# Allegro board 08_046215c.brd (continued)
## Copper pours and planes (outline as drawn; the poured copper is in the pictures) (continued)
GND on L2_GROUND: 12.9,24.98 13.49,25.16 14.2,25.16 14.2,26.76 13.46,26.76 12.98,26.93 9.96,26.93 9.12,26.81 8.38,26.38 4.83,22.82 0.51,22.82 0.51,30.06 0.63,29.93 10.41,29.93 10.41,31.58 18.8,31.58 22.48,35.27 25.27,35.27 24.77,34.76 24.77,32.73 25.65,32.73 25.78,32.85 25.78,34 26.42,34.63 26.67,34.63 27.3,34 27.3,32.73 28.32,32.73 28.32,34.63 27.18,35.77 27.05,35.77 27.05,43.65 26.67,44.03 22.1,44.03 19.43,46.7 14.99,46.7 14.99,55.33 9.78,55.33 9.78,48.73 0.51,48.73 0.51,65.49 27.43,65.49 27.56,65.62 27.56,68.29 27.69,68.41 75.95,68.41 75.95,0.47 22.86,0.47 22.86,3.14 11.94,3.14 11.94,5.29 0.51,5.29 0.51,20.84 4.93,20.84 5.52,20.95 6.05,21.25 9.65,24.85 9.78,24.95 9.93,24.98 ; 4 cut-outs
GND on L3_SIGNAL: 23.5,0.34 23.5,0.47 22.99,0.47 22.99,3.14 11.94,3.14 11.94,5.42 0.51,5.42 0.51,29.3 11.05,29.3 11.05,34.25 24,34.25 26.29,36.66 26.92,37.3 29.21,34.25 29.21,31.33 31.37,30.44 31.37,26.63 33.91,26.63 33.91,32.85 32.13,33.62 32.13,41.49 32.77,41.49 32.77,43.01 33.27,43.01 33.27,51.01 29.97,51.01 27.56,57.49 27.56,63.59 25.02,63.59 25.02,63.33 24.36,62.67 24.36,52.53 25.27,48.22 27.56,48.22 27.56,44.41 11.18,44.41 11.18,49.36 0.51,49.36 0.51,64.98 27.56,64.98 27.56,68.54 27.69,68.67 75.95,68.67 75.95,49.87 75.82,49.87 75.82,0.34 ; 6 cut-outs
GND on L4_GROUND, L7_GROUND: 27.56,68.41 75.95,68.41 75.95,0.47 22.86,0.47 22.86,3.14 11.94,3.14 11.94,5.29 0.51,5.29 0.51,65.49 27.43,65.49 27.56,65.62
GND on L6_POWER: 0.38,58.89 13.84,58.89 13.84,61.17 34.29,61.17 34.29,55.21 25.15,55.21 24.38,54.44 24.38,35.27 25.27,34.38 27.43,34.38 27.43,34.25 27.94,33.74 39.88,33.74 39.88,25.23 24.13,25.23 24.13,5.93 24,5.8 18.29,5.8 18.29,8.47 13.21,8.47 13.21,11.39 13.08,11.52 10.03,11.52 10.03,17.36 0.38,17.36
GND on L9_GROUND: 27.56,68.41 75.95,68.41 75.95,0.47 23.37,0.47 23.37,3.14 11.94,3.14 11.94,5.29 0.51,5.29 0.51,65.49 27.56,65.49
GND on L10_SIGNAL: 27.56,68.41 75.95,68.41 75.95,0.47 23.37,0.47 23.37,3.14 11.94,3.14 11.94,5.29 0.51,5.29 0.51,65.49 27.56,65.49 ; 19 cut-outs
GND on L11_GROUND: 27.56,68.41 75.95,68.41 75.95,0.47 23.37,0.47 23.37,3.14 11.94,3.14 11.94,5.29 0.51,5.29 0.51,65.49 27.56,65.49 ; 1 cut-out
SVDD12 on TOP (solid shape): 32.7,56.33 33.3,56.33 33.84,55.78 33.84,55.69 33.93,55.69 34.61,55.01 34.61,54.99 34.65,54.73 34.8,54.52 34.8,51.01 32.95,51.01 32.51,51.27 32.07,51.01 31.68,51.01 31.24,51.27 30.8,51.01 30.48,51.01 30.1,51.4 30.1,55.33 30.61,55.84 32.39,55.84 32.47,55.93 32.55,55.93 32.55,56.26 32.62,56.33
SVDD12 on L8_POWER: 29.46,55.46 31.24,57.24 37.72,57.24 39.5,55.46 39.5,35.39 29.46,35.39
VCC on L5_POWER: 0.63,50.25 0.63,65.37 25.53,65.37 25.53,62.95 19.3,62.95 19.3,50.25
VDDA12 on TOP: 20.07,53.17 20.07,55.46 20.45,55.84 22.35,55.84 22.48,55.97 22.48,56.22 22.61,56.35 23.37,56.35 23.62,56.09 23.62,54.82 23.37,54.57 23.37,53.3 23.11,53.05 20.19,53.05
VDDA12 on L8_POWER: 24.38,57.36 26.42,55.33 26.42,42.51 25.65,41.74 20.32,41.74 19.56,42.51 19.56,55.71 21.21,57.36
VDDA25 on TOP (solid shape): 22,43.39 24.06,41.92 25.1,40.97 25.1,40.97 25.16,40.9 25.23,40.85 25.24,40.84 25.4,40.7 25.58,40.52 25.59,40.51 25.65,40.4 25.75,40.34 25.76,40.34 26.08,40.02 26.09,40.01 26.15,39.9 26.25,39.84 26.26,39.84 26.42,39.68 26.42,39.02 26.42,39 26.24,38.82 26.23,38.82 26.15,38.76 26.09,38.68 26.09,38.67 25.74,38.32 25.73,38.32 25.65,38.26 25.6,38.18 25.59,38.18 25.4,37.98 25.2,37.81 25.16,37.77 25.12,37.73 24.05,36.76 21.97,35.27 20.95,35.27 20.95,37.68 23.75,37.68 25.27,38.67 25.35,38.72 25.52,38.72 25.55,38.72 25.62,38.76 25.67,38.81 25.7,38.88 25.7,38.95 25.7,39.71 25.71,39.74 25.66,39.89 25.53,39.96 25.37,39.97 25.28,40.01 24,40.85 20.95,40.85 20.95,43.39
VDDA25 on TOP: 9.4,56.73 9.65,56.73 9.65,55.08 14.35,55.08 14.35,51.27 11.05,51.27 11.05,52.92 9.02,52.92 9.02,55.21 9.4,55.59
VDDA25 on TOP: 8.64,43.39 8.64,35.27 20.95,35.27 20.95,37.81 20.19,37.81 20.19,40.85 20.95,40.85 20.95,43.39
VDDA25 on L2_GROUND: 10.03,31.96 18.67,31.96 22.48,35.77 26.54,35.77 26.54,43.52 21.46,43.52 18.67,46.32 14.48,46.32 14.48,55.08 10.16,55.08 10.16,48.35 0.51,48.35 0.51,40.35 17.14,40.35 17.53,38.7 17.14,37.04 14.61,37.04 14.61,38.31 0.51,38.31 0.51,30.31 10.03,30.31 ; 1 cut-out
VDDA25 on L3_SIGNAL: 8.64,43.39 27.05,43.39 27.05,37.81 26.92,37.81 24.38,35.27 8.64,35.27
VDDC12 on TOP: 23.88,54.57 27.69,52.41 27.69,47.71 23.88,50.13
VDDC12 on L6_POWER: 30.48,43.9 28.07,41.49 28.07,35.65 27.69,35.65 27.43,35.9 27.43,36.28 26.92,36.92 26.92,41.24 27.43,41.74 27.43,43.39 26.04,44.79 26.04,51.27 26.92,52.16 28.7,52.16 30.48,50.38
VIN_12V on BOTTOM (solid shape): 54.48,33.49 53.09,33.49 53.09,32.85 50.67,32.85 50.67,31.96 50.16,31.94 49.96,31.92 49.78,31.94 49.53,31.96 49.53,32.73 49.15,32.73 49.15,33.74 51.56,33.74 52.58,34.76 53.09,35.39 54.48,35.39
VIN_12V on BOTTOM: 51.31,19.14 51.31,14.57 54.74,14.57 54.74,19.14
VIN_12V on BOTTOM: 53.85,45.3 53.85,44.16 54.61,43.78 54.61,42 54.99,41.62 55.75,41.62 55.75,43.27 55.37,43.65 55.37,45.68 54.36,45.68 54.36,45.3
VIN_12V on BOTTOM: 40.89,36.03 42.29,34.63 43.05,34 43.05,31.2 42.67,31.2 42.16,31.71 42.16,33.62 41.15,33.62 41.15,33.87 41.02,34 38.86,34 38.86,36.03
VIN_12V on L8_POWER: 50.16,13.93 50.16,19.14 41.28,19.26 41.28,20.66 41.02,52.28 41.02,56.09 38.86,58.25 21.46,58.25 18.92,55.71 18.92,52.79 18.41,52.28 15.11,52.28 13.84,53.55 12.57,53.55 8,58.13 8,65.49 10.16,65.49 10.16,58.63 13.34,55.46 16.89,55.46 21.84,60.41 40,60.41 43.05,57.36 43.05,52.79 53.47,52.79 53.98,52.28 53.98,48.98 54.74,48.09 54.74,45.93 55.88,44.79 55.88,13.93
3P3VAUX on TOP: 72.9,56.73 73.91,56.73 74.42,56.35 74.42,55.59 73.91,55.08 72.9,55.08
3P3VAUX on L5_POWER: 68.83,66.25 68.83,21.55 68.45,21.17 68.45,19.65 68.83,19.26 75.95,19.26 75.95,66.25
AD9508_VDD on TOP: 43.81,12.91 43.81,10.5 45.59,10.5 45.59,12.91
AD9508_VDD on TOP: 49.15,13.04 51.05,13.04 51.05,11.77 50.04,11.77 50.04,10.5 48.77,10.5 48.77,12.15 48.26,12.15 48.26,13.04 48.13,13.17 48.13,16.09 50.04,16.09 50.29,15.84 50.29,14.95 49.53,14.18 49.15,14.18 49.02,14.06 49.02,13.17
AD9508_VDD on L5_POWER: 41.28,1.74 52.45,1.74 52.45,12.66 43.18,12.66 43.18,10.76 41.28,10.76
ADCLK914VCC on TOP: 11.18,20.53 12.45,20.53 12.45,19.39 13.59,19.39 13.59,19.01 11.56,19.01 11.56,20.03 11.18,20.03
ADCLK914VCC on L8_POWER: 10.29,6.82 10.29,22.44 18.03,22.44 18.03,17.74 16.26,17.74 16.26,6.82
ADF4355_VDD_3V3 on TOP: 10.79,14.06 12.83,14.06 12.83,12.53 10.79,12.53
ADF4355_VDD_3V3 on L10_SIGNAL: 32.13,6.44 33.27,7.58 33.27,13.17 38.23,13.17 38.99,12.41 45.85,12.41 46.99,13.55 46.99,18.38 46.61,18.76 31.12,18.76 28.32,15.96 24.77,15.96 24.26,16.34 24.26,18.38 24,18.63 10.67,18.63 8.89,16.85 8.89,11.64 14.1,6.44
ADF4355_VRF_3V3 on TOP: 18.92,11.39 18.92,9.49 15.75,9.49 15.75,11.39
ADF4355_VRF_3V3 on TOP: 17.14,15.45 19.69,15.45 19.69,15.71 20.57,15.71 20.57,15.45 21.59,15.45 21.59,14.06 21.34,13.8 21.34,13.42 21.46,13.3 22.23,13.3 22.23,12.91 21.08,12.91 20.83,13.17 20.83,13.8 18.54,13.8 18.54,13.42 17.14,13.42
ADF4355_VRF_3V3 on BOTTOM: 16.51,11.52 16.51,9.74 15.24,8.47 15.24,6.56 13.97,5.29 11.81,5.29 11.81,7.33 13.46,7.33 13.46,9.49 15.49,11.52
ADF4355_VRF_3V3 on L5_POWER: 20.7,15.58 21.72,14.57 21.72,5.55 18.16,5.55 18.16,8.22 12.95,8.22 12.95,15.96 15.37,18.38 20.7,18.38
ADF4355_VVCO_5V on TOP: 37.85,6.18 39.75,6.18 39.75,4.91 37.59,4.91 37.34,5.04 37.34,5.8
ADF4355_VVCO_5V on TOP: 21.59,7.83 23.5,7.83 23.75,8.09 23.75,8.85 22.48,8.85 22.23,9.1 22.23,9.36 20.95,9.36 20.83,9.23 20.83,8.09 21.59,8.09
ADF4355_VVCO_5V on L8_POWER: 19.43,3.14 39.75,3.14 39.75,7.96 23.62,7.96 23.62,24.73 18.92,24.73 18.92,7.58 19.43,7.07
ADP5054_1V2 on TOP (solid shape): 57.91,38.06 57.15,38.06 56.73,37.64 56.57,37.64 56.57,37.48 55.24,36.16 54.36,36.16 53.34,37.17 53.34,37.55 52.7,38.19 52.7,39.33 57.91,39.33
ADP5054_1V2 on BOTTOM: 55.88,38.06 55.88,35.77 53.47,35.77 53.47,38.06
ADP5054_1V2 on L5_POWER: 34.8,45.55 40.39,40.35 43.31,40.35 46.74,43.78 53.47,43.78 57.02,40.22 57.02,34.5 56.77,34.25 28.19,34.25 28.19,41.49 32.39,45.55
ADP5054_1V5 on TOP: 30.61,58.13 32.64,58.13 33.02,58.51 34.92,58.51 34.92,59.52 33.4,61.05 30.48,61.05 30.1,60.67 30.1,58.63
ADP5054_1V5 on TOP: 20.57,58.13 22.61,58.13 22.61,57.62 23.37,57.62 23.62,57.87 23.62,58.38 23.75,58.51 24.89,58.51 24.89,61.43 20.45,61.43 20.07,61.05 20.07,58.63
ADP5054_1V5 on BOTTOM: 40.39,42.51 40.39,42.89 37.72,42.89 37.72,43.39 36.83,43.39 36.83,44.16 37.85,44.16 37.85,45.3 40.89,45.3 40.89,43.78 41.15,43.78 42.04,42.89 42.04,42.51
ADP5054_1V5 on L5_POWER: 37.72,44.66 37.72,43.9 39.37,42.25 43.31,42.25 43.81,42.76 43.81,53.05 34.29,62.57 21.59,62.57 20.7,61.68 20.7,58.63 26.67,52.67 29.72,52.67
ADP5054_3V8 on TOP: 9.65,60.92 9.65,60.29 9.14,60.29 9.14,59.02 7.62,59.02 7.62,58.63 6.1,58.63 5.21,59.52 5.21,61.17 9.4,61.17
ADP5054_3V8 on TOP: 34.29,63.84 35.69,63.84 36.2,64.35 36.2,64.86 36.32,64.98 38.1,64.98 38.61,64.48 42.29,64.48 42.42,64.35 42.42,63.46 41.53,62.57 38.61,62.57 37.97,63.21 34.29,63.21
ADP5054_3V8 on TOP: 14.22,5.04 14.22,3.01 16.89,3.01 16.89,5.04
ADP5054_3V8 on BOTTOM: 54.99,20.66 57.66,20.66 57.66,21.04 59.31,21.04 59.31,18.25 57.28,18.25 57.28,16.72 56.64,16.09 55.12,16.09 54.99,16.22
ADP5054_3V8 on BOTTOM: 42.67,64.73 42.67,63.08 41.28,63.08 40.89,62.7 40.89,61.3 39.24,61.3 39.12,61.43 39.12,63.46 38.1,63.46 38.1,64.73
ADP5054_3V8 on L6_POWER: 55.12,68.03 55.12,36.16 57.53,33.74 57.53,17.23 54.48,14.18 42.55,14.18 42.55,11.39 29.84,11.39 29.72,0.85 22.99,0.85 22.99,3.39 12.07,3.39 12.07,6.18 6.86,6.18 6.86,16.34 9.4,16.34 12.57,13.3 17.78,7.96 24.13,7.96 24.64,8.47 24.64,24.6 41.15,24.6 41.15,65.11 33.78,65.11 33.78,63.21 32.39,61.81 13.34,61.81 13.34,59.65 4.32,59.65 4.32,64.6 27.05,64.6 28.19,65.75 28.19,68.03
ADP5054_5V5 on TOP: 38.86,13.3 38.86,11.14 40.89,11.14 40.89,13.3
ADP5054_5V5 on BOTTOM: 33.02,22.06 33.02,23.96 34.8,23.96 34.8,23.33 36.58,23.33 36.58,22.06
ADP5054_5V5 on L5_POWER: 30.73,24.22 51.82,24.22 51.82,14.06 50.8,13.04 42.04,13.04 42.04,11.26 30.73,11.26
ADP5073_2V2 on BOTTOM: 36.07,51.9 39.75,51.9 39.75,50.25 37.47,50.25 37.47,50.13 36.07,50.13
FMCA_VCC_12P0V on TOP (solid shape): 59.26,10.63 59.36,10.55 59.31,10.44 58.98,8.8 60.65,8.8 60.74,8.83 60.82,8.78 61.74,8.88 61.04,9.49 60.94,9.5 60.89,9.58 60.72,10.08 60.33,10.44 60.28,10.55 60.38,10.63 61.59,10.63 61.98,10.25 61.98,5.29 61.85,5.17 58.93,5.17 58.93,6.18 55.12,6.18 55.12,9.99 55.75,10.63
FMCA_VCC_12P0V on BOTTOM: 51.69,5.29 51.69,1.23 57.4,1.23 57.4,5.29
FMCA_VCC_12P0V on L5_POWER: 71.75,0.6 53.59,0.6 53.59,12.15 60.2,18.76 71.75,18.76
HMC365_VDD on TOP: 34.04,6.69 34.04,7.83 34.16,7.83 34.16,9.23 31.62,9.23 31.62,5.8 33.27,5.8 33.27,6.69
HMC365_VDD on BOTTOM: 29.84,7.83 30.35,7.83 30.35,6.31 31.24,6.31 31.24,8.09 32.51,8.09 32.51,6.56 31.88,6.56 31.88,4.91 29.84,4.91
HMC849_VDD on TOP: 18.92,24.22 19.81,24.22 20.19,23.84 20.19,23.33 24,23.33 24,22.57 18.92,22.57
HMC849_VDD on L5_POWER: 12.7,16.34 12.7,11.64 9.65,11.64 9.65,24.34 20.7,24.34 20.7,21.93 18.29,21.93
OUT_N on TOP (solid shape): 25.4,38.95 25.3,38.92 23.88,38.06 20.83,38.06 20.83,39.08 23.62,39.08 23.88,38.95 25.15,39.2 25.4,39.2
OUT_P on TOP (solid shape): 25.3,39.76 25.4,39.71 25.4,39.46 25.3,39.43 25.2,39.43 23.9,39.66 23.62,39.46 20.83,39.46 20.83,40.47 24,40.47
SA_GND on TOP: 0.51,30.31 10.03,30.31 10.03,34.5 8,34.5 8,38.44 0.51,38.44
SA_GND on TOP: 0.51,48.35 10.16,48.35 10.16,44.16 8,44.16 8,40.09 0.51,40.09
SA_GND on BOTTOM: 0.51,48.35 0.51,30.31 11.56,30.31 11.56,44.03 10.16,44.03 10.16,48.35
SA_GND on L3_SIGNAL: 0.25,48.35 0.25,30.31 10.03,30.31 10.03,34.5 8,34.5 8,44.16 10.16,44.16 10.16,48.35
SPI33 on TOP: 29.59,62.83 29.59,61.17 25.65,61.17 25.65,62.83
SPI33 on L3_SIGNAL: 31.88,27.14 31.88,30.95 29.72,31.71 29.72,48.6 25.91,48.6 25.15,52.27 25.15,62.57 26.92,62.57 26.92,57.36 28.32,53.3 29.59,50.25 32.77,50.25 32.77,43.39 32.39,43.39 32.39,41.87 31.62,41.87 31.62,33.23 33.4,32.47 33.4,27.14
SUPPLY33 on TOP: 29.84,64.35 33.02,64.35 33.27,64.1 33.27,61.94 32.89,61.56 30.86,61.56 29.72,62.7 29.72,64.22
SUPPLY33 on BOTTOM: 48.13,59.52 48.13,57.36 55.24,57.36 55.37,57.62 55.63,58 55.63,59.52
SUPPLY33 on L8_POWER: 12.19,65.62 27.94,65.62 27.94,68.29 75.95,68.29 75.95,5.8 56.52,5.8 56.51,7.45 51.82,7.45 47.5,11.77 47.5,16.47 46.99,16.98 46.99,18.63 49.53,18.63 49.53,13.17 49.53,13.17 56.48,13.17 56.39,33.49 56.26,43.39 56.26,45.17 55.37,46.06 55.37,52.92 53.98,54.32 47.24,54.32 45.97,55.59 45.97,58.38 43.18,61.17 21.97,61.17 16.89,56.09 13.84,56.09 12.19,57.75
SVSYNC33 on BOTTOM: 39.88,54.95 40.64,54.95 40.64,53.3 38.48,53.3 38.48,58.13 38.35,58.25 36.96,58.25 36.83,58.38 36.83,59.65 37.97,59.65 39.88,57.75
SVSYNC33 on L10_SIGNAL: 37.72,54.19 38.35,54.95 40.77,54.95 40.77,37.68 39.37,36.28 31.88,36.28 31.12,37.04 31.12,44.16 33.15,46.19 34.67,46.19 37.72,49.24
SW1 on BOTTOM: 48.9,34 48.9,32.73 47.62,32.73 47.62,33.62 48.26,34 48.26,35.27 48.01,35.27 48.01,36.28 46.35,36.28 46.35,37.3 46.61,37.3 46.61,37.81 52.07,37.81 52.07,35.01 51.18,34
SW2 on BOTTOM: 44.83,32.73 43.69,32.73 43.31,33.11 43.31,34.12 42.42,34.89 41.91,35.39 41.91,37.17 44.7,37.17 44.7,37.3 46.1,37.3 46.1,36.28 45.85,36.28 45.85,35.65 45.59,35.39 44.45,35.39 44.45,34.12 44.83,33.74
UNNAMED_3_ADM7150_I1277_EN on BOTTOM: 29.46,12.66 32.89,12.66 32.89,11.14 30.86,11.14 30.86,9.99 29.97,9.99 29.97,11.52 29.46,11.52
UNNAMED_3_ADM7150_I1277_REF on BOTTOM: 28.07,12.28 29.08,12.28 29.08,11.14 29.21,11.01 29.72,11.01 29.72,9.99 28.45,9.99 28.19,10.25 28.19,11.14 28.07,11.26
UNNAMED_4_ADP5054_I1011_SW31 on BOTTOM: 47.12,26.63 47.75,26.63 47.75,25.23 48.13,25.23 48.13,23.96 48.9,23.96 48.9,20.03 49.28,19.77 47.12,19.77
UNNAMED_4_ADP5054_I1011_SW41 on BOTTOM: 45.09,26.63 45.85,26.63 45.85,21.3 44.58,21.3 44.58,25.36 45.09,25.36
UNNAMED_4_ADP5073_I1002_SW on BOTTOM: 42.55,46.19 45.72,46.19 45.72,45.68 45.97,45.43 48.26,45.43 48.51,45.68 48.51,46.19 49.4,46.19 49.53,46.06 49.53,45.43 49.66,45.3 50.8,45.3 51.31,45.68 52.2,45.68 52.2,44.03 43.43,44.03 42.55,44.92
UNNAMED_4_ADP7183_I808_VIN on BOTTOM: 20.83,61.81 21.84,61.81 22.1,61.56 22.1,60.16 23.5,60.16 23.5,58.89 23.37,58.76 21.34,58.76 21.21,58.63 21.21,58 19.3,58 19.3,59.02 19.43,59.14 20.7,59.14 20.83,59.27
UNNAMED_4_CAP_I904_N2 on BOTTOM: 37.59,49.62 43.69,49.62 43.69,48.22 39.62,48.22 39.5,48.09 37.59,48.09
UNNAMED_4_CAP_I948_N2 on BOTTOM: 49.78,19.52 49.78,23.2 50.55,23.96 52.2,23.96 52.58,24.34 52.96,24.34 53.34,24.73 53.34,25.61 53.21,25.74 52.7,25.74 52.32,26.12 52.32,26.88 52.45,27.01 53.47,27.01 53.85,26.63 53.85,24.98 54.23,24.6 56.9,24.6 57.15,24.34 57.15,20.92 54.74,20.92 54.74,21.93 54.86,22.06 54.74,22.19 52.45,22.19 51.69,21.42 51.69,19.52
UNNAMED_4_CAP_I949_N2 on BOTTOM: 44.32,23.84 41.4,23.84 41.15,24.09 37.85,24.09 37.08,23.33 37.08,21.8 37.21,21.68 42.8,21.68 42.8,21.17 42.93,21.04 44.32,21.04
UNNAMED_4_CAP_I1125_N1 on BOTTOM: 57.66,39.97 57.66,38.7 56.64,38.7 56.52,38.57 54.74,38.57 54.36,38.19 47.88,38.19 47.88,40.22 49.66,40.22 49.66,42.63 51.18,42.63 51.18,40.22 52.45,40.22 52.45,39.97
UNNAMED_4_CAP_I1127_N1 on BOTTOM: 39.37,38.44 44.58,38.44 44.58,41.36 44.2,41.74 41.4,41.74 41.15,42 38.61,42 38.1,41.62 38.1,39.46
UNNAMED_5_ADCLK914_I223_VREF on TOP: 10.79,17.11 13.59,17.11 13.59,18.25 12.57,18.25 12.57,18.5 10.79,18.5
UNNAMED_5_ADM7150_I186_REF on TOP: 38.73,9.99 40.13,9.99 40.13,9.61 41.78,9.61 41.78,10.76 38.73,10.76
UNNAMED_5_ADM7150_I186_VIN on TOP: 34.92,10.37 36.83,10.37 37.21,9.99 38.48,9.99 38.48,12.91 35.81,12.91 35.81,11.64 34.92,11.64
UNNAMED_5_ADM7154_I181_REF on BOTTOM: 1.65,12.66 2.79,12.66 2.79,14.06 3.05,14.31 3.05,15.2 1.65,15.2
UNNAMED_5_ADM7154_I181_VIN on BOTTOM: 3.05,12.66 6.73,12.66 6.73,11.9 9.91,11.9 9.91,14.06 7.75,14.06 7.62,14.18 7.62,14.44 5.97,14.44 5.97,13.68 3.05,13.68
UNNAMED_5_ADM7154_I181_VOUT on BOTTOM: 3.05,9.36 7.11,9.36 7.11,11.26 8.26,11.26 8.26,5.68 4.45,5.68 4.45,7.83 3.05,7.83
UNNAMED_5_ADM7154_I297_EN on TOP: 12.7,8.22 14.1,8.22 14.1,6.82 16,6.82 16,5.42 12.7,5.42
UNNAMED_5_ADM7154_I297_REF on TOP: 10.67,8.22 12.45,8.22 12.45,5.93 10.67,5.93
UNNAMED_5_CAP_I329_N1 on TOP: 16.76,9.1 18.41,9.1 18.67,8.85 18.67,4.41 18.03,4.41 18.03,5.29 16.76,6.56
VADJ on L6_POWER: 55.63,50 69.34,50 69.34,8.22 60.83,8.22 60.83,12.15 64.39,15.71 64.39,42.25 55.63,42.25
VNEG12 on TOP (solid shape): 25.37,41.69 25.61,41.46 25.65,41.4 25.71,41.36 26.11,40.96 26.15,40.9 26.21,40.86 26.39,40.68 27.05,39.97 27.05,38.7 27.03,38.67 26.47,38.09 26.39,37.98 26.22,37.82 26.15,37.76 26.1,37.69 25.72,37.31 25.65,37.26 25.6,37.19 25.4,36.99 25.33,36.96 24.83,36.96 24.72,37.08 24.77,37.2 25.27,37.69 25.46,37.86 25.51,37.9 25.54,37.95 25.97,38.37 26.01,38.4 26.04,38.45 26.27,38.67 26.33,38.67 26.7,38.9 26.66,39.33 26.7,39.77 26.33,40 26.28,40 25.49,40.79 25.2,41.06 24.77,41.48 24.78,41.6 24.84,41.69
VNEG12 on BOTTOM: 16.13,53.05 16.13,54.19 20.7,54.19 20.7,52.92 22.99,52.92 22.99,50.38 22.86,50.25 18.16,50.25 18.16,50.13 14.73,50.13 14.73,51.65
VNEG12 on L10_SIGNAL: 1.14,52.79 13.72,52.79 14.25,53.3 15.24,53.3 18.16,50.38 24.64,50.38 25.53,49.49 25.53,44.79 27.18,43.14 27.18,35.27 26.54,34.63 11.43,34.63 11.43,29.68 1.27,29.68
VOUT on BOTTOM: 20.32,57.75 21.46,57.75 21.46,56.86 22.1,56.86 22.1,54.7 21.97,54.7 21.97,53.3 20.95,53.3 20.95,54.7 20.83,54.7 20.83,56.6 20.32,56.6
VREG on L5_POWER: 37.34,33.11 37.34,24.47 54.99,24.47 54.99,33.11

Small or netless copper shapes (teardrops, artwork), in the pictures only: 1 on TOP

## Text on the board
Ref Des/Silkscreen Top: PWR ERR | PLL STAT | B | A | OSC EN | PRIMARY SIDE | 08-046215 REV C Z | EXT CLK | REF IN | DAC IRQ | AD9162-FMCB-EBZ | AD9164-FMCB-EBZ | USB STAT | 12V PWR | GND PWR | USB
PAGE_OUTLINE: C1 | CHANGES PER ECR-092664 | 13FEB20 | 30MAY18 | J.AUSTRIA | S.B. | EVALUATION BOARD
DIMENSION: 15.    INDICATED VIAS TO BE NON-CONDUCTIVE EPOXY FILLED, AND GROUND FLUSH PRIOR | TO OVER PLATING. | DIFFERENTIAL IMPEDENCE 100 OHMS +/- 10% | ARTWORK LINE WIDTH FOR | IMPEDANCE CONTROLLED LINES = 0.005" | 1 | 3 PLCS | R.039 | 2.413 | .453 | .425 | SEE NOTE 15 | C | 09-046215
User.8: L2 GROUND | 08-      -07
User.9: L3 SIGNAL | 08-      -08
User.10: NOTES: | FABRICATION: | 16.    BOARDS TO BE PANELIZED AND SHIPPED INTACT. | IMMERSION GOLD OVER 100-200 MICROINCHES OF ELECTROLESS NICKEL. | FR-4, IN ACCORDANCE WITH IS410 (LATEST REV.). GLASS FABRIC | 14.    FINISH: SURFACES SHALL HAVE ENIG FINISH PLATED WITH 2-6 MICROINCHES OF | MATERIALS;     ROGERS 4350. | BASE, EPOXY RESIN, FIRE RESISTANT. | BONDING AGENT; PREIMPREGNATED B STAGE EPOXY GLASS CLOTH IN ACCORDANCE WITH | IPC-L-109 (LATEST REV.). | CLADDING;      EXTERNAL LAYERS 1/2 OZ. COPPER, OVERPLATE TO 1 1/2 OZ. | INTERNAL SIGNAL LAYERS 1 OZ. COPPER. | INTERNAL PLANE LAYERS 1 OZ. COPPER. | SOLDER MASK;   SHALL BE LIQUID PHOTOIMAGABLE (LPI) APPLIED ON BOTH SIDES OVER | BARE COPPER AND SHALL MEET IPC-SM-840 (LATEST REV.) CLASS 3. | COLOR: BLUE. | SILK SCREEN;   SHALL BE PERMANENT NON-CONDUCTIVE EPOXY INK, COLOR WHITE. | U.L. RATING;   94VO MINIMUM. | 1.    REFER TO IPC-6010 SERIES (LATEST REV.), CLASS 2 FOR FABRICATION UNLESS | OTHERWISE SPECIFIED. | 2.    UNDIMENSIONED HOLES TO BE LOCATED WITHIN +/-.005 OF THEIR TRUE POSITION | WITH RESPECT TO ARTWORK. | 3.    PLATED HOLE WALL THICKNESS SHALL NOT BE LESS THAN .001 INCH MINIMUM | AVERAGE, WITH NO READING LESS THAN .0008 BY CROSS SECTION. | 4.    HOLE DIAMETERS APPLY AFTER PLATING. | 5.    FINISHED CONDUCTOR WIDTHS SHALL NOT BE REDUCED FROM THE NOMINAL, | INDICATED ON THE MASTER PATTERN, BY MORE THAN THE CONDUCTOR THICKNESS. | 6.    MINIMUM DESIGN LINE WIDTH IS .005 INCH. | 7.    MINIMUM DESIGN SPACING IS .005 INCH. | 8.    BOARD/PANEL MUST MEET IPC-A-600 (LATEST REV.) CLASS 2 FOR FLATNESS. | 9.    MFGR. TO LEGIBLY ETCH OR STAMP/SCREEN WITH PERMANENT NON-CONDUCTIVE INK | ON SECONDARY SIDE IN A CLEAR AREA UNLESS OTHERWISE INDICATED; | A. U.L. CODE             D. MFGR. LOGO | B. DATE CODE (STAMP)     E. SUCCESSFUL ELECTRICAL BOARD TEST. | C. FLAMMABILITY RATING | 10.    NON-FUNCTIONAL PADS MAY BE REMOVED FROM INNER SIGNAL LAYERS AT MFGR. | DISCRETION. | 11.    IF PAD SIZES PROVIDED ARE NOT LARGE ENOUGH TO MAINTAIN ANNULAR RING | REQUIREMENT, MFGR. MAY TEAR DROP PADS TO MAINTAIN ANNULAR RING AT PAD | TO CIRCUIT INTERFACE ONLY AND MUST INSURE ELECTRICAL INTEGRITY. | 12.    REPAIRS PER IPC-R-700 ARE ALLOWED. | 13.    MODIFICATIONS TO THE ARTWORK, OTHER THAN THOSE DESCRIBED ON THE | FABRICATION DRAWING, ARE NOT ALLOWED WITHOUT WRITTEN AUTHORIZATION.
User.11: L4 GROUND | 08-      -09
User.12: L5 POWER | 08-      -10
User.14: L6 POWER | 08-      -11
User.15: L7 GROUND | 08-      -12
User.16: L8 POWER | 08-      -13
User.17: L9 GROUND | 08-      -14
User.18: ROGERS 4350 | ROGERS
User.19: L10 SIGNAL | 08-      -15
User.20: L11 GROUND | 08-      -16
User.25: 01-046215
User.31: PRIMARY SIDE
User.38: FIGURE | SIZE | 5.0 | 10.0 | 12.0 | 28.0 | 40.0 | 45.0 | 63.0 | 105.0 | 50.0 | 75.0x28.0 | 83.0x28.0 | DRILL CHART: TOP to BOTTOM | FINISHED HOLES IN MILS | PLATED | NON-PLATED | QTY | 141 | 342 | 349 | 5 | 7 | 8 | 1 | 2 | TOLERANCE/NOTES
User.39: FIGURE | SIZE | 8.0 | DRILL CHART: TOP to L2_GROUND | FINISHED HOLES IN MILS | PLATED | QTY | 133 | TOLERANCE/NOTES
User.40: FIGURE | SIZE | 8.0 | DRILL CHART: L11_GROUND to BOTTOM | FINISHED HOLES IN MILS | PLATED | QTY | 67 | TOLERANCE/NOTES
User.41: FIGURE | SIZE | 10.0 | DRILL CHART: L2_GROUND to L11_GROUND | FINISHED HOLES IN MILS | PLATED | QTY | 10 | TOLERANCE/NOTES
User.42: VIAS FROM LAYER 1 TO LAYER 2
User.43: 3 | 4 | VIAS FROM LAYER 2 TO LAYER 11
User.44: 4 | VIAS FROM LAYER 11 TO LAYER 12
User.45: 4
